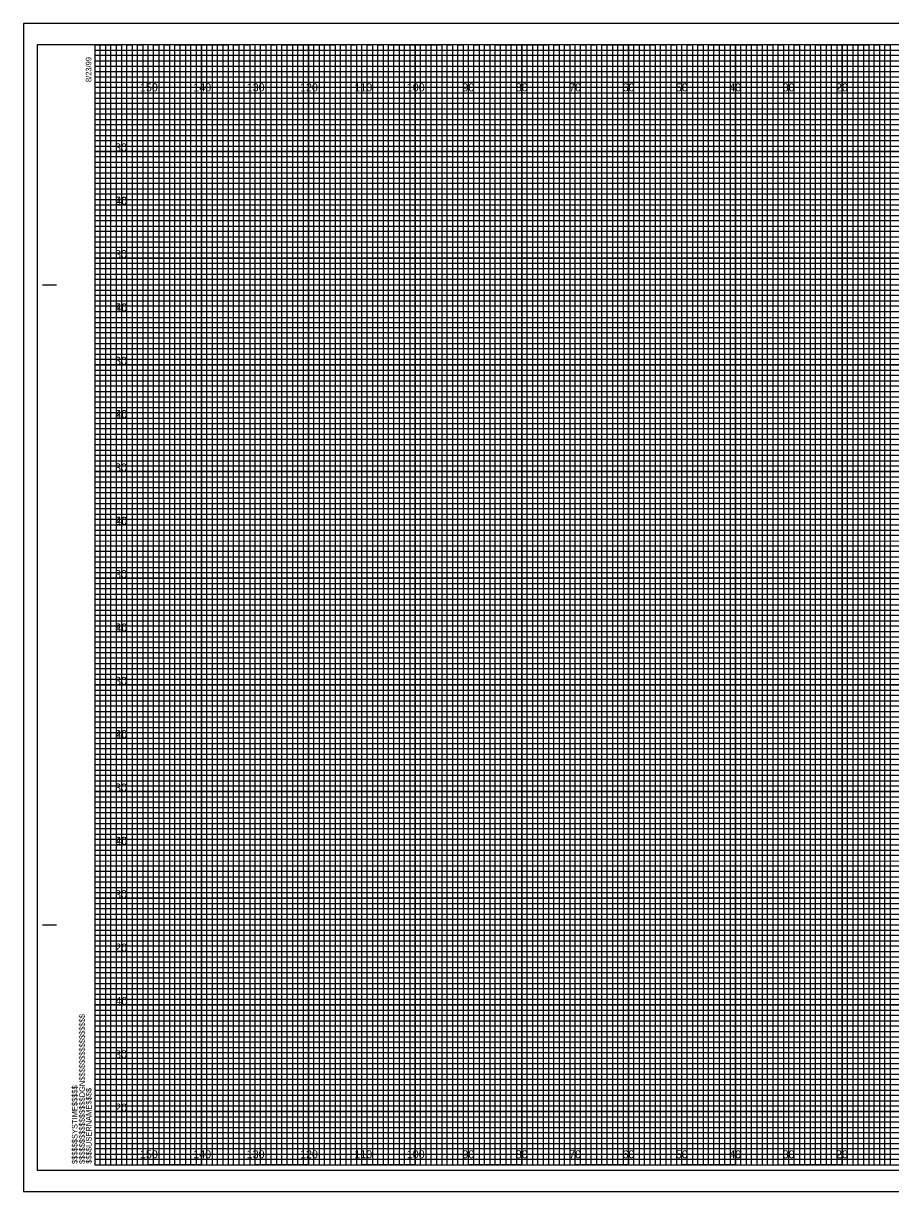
# Model space of a CAD drawing. Extents: x -13 to 323, y 215 to 434.
# Drawn here: x -13.4 to 149.1, y 215 to 434 of the extents above; entities that cross this region are included whole.
import ezdxf

# ---------------------------------------------------------------- set-up
doc = ezdxf.new("R2010")
doc.units = 0
for name, color, linetype in [('Prop XS Elevation Labels', 7, 'Continuous'), ('Prop XS Offset Labels', 7, 'Continuous'), ('Sheet Cross Section CELL', 7, 'Continuous'), ('Sheet Cross Section Grid Major CELL', 7, 'Continuous'), ('Sheet Cross Section Grid Middle CELL', 7, 'Continuous'), ('Sheet Cross Section Grid Minor 1 CELL', 7, 'Continuous'), ('Sheet Cross Section Grid Minor 2 CELL', 7, 'Continuous'), ('Sheet Cutting Line CELL', 7, 'Continuous'), ('Sheet DOT Grid CELL', 7, 'Continuous'), ('Sheet Plot Border Inside CELL', 7, 'Continuous'), ('Sheet Plot Border Outside CELL', 7, 'Continuous')]:
    doc.layers.add(name, color=color, linetype=linetype)

msp = doc.modelspace()

# ---------------------------------------------------------------- linework, layer by layer
at = {"layer": 'Sheet Cross Section CELL'}
for p, q in [((-9.8, 385), (-7.3, 385)), ((-9.7, 385), (-7.2, 385)), ((-9.8, 265), (-7.3, 265)), ((-9.7, 265), (-7.2, 265)), ((0, 220), (0, 220)), ((0, 220), (0, 220)), ((0, 220), (0, 220)), ((0, 220), (0, 220)), ((0, 220), (0, 220)), ((0, 220), (0, 220)), ((0, 220), (0, 220))]:
    msp.add_line(p, q, dxfattribs=at)
msp.add_lwpolyline([(320, 430), (0, 430), (0, 220), (320, 220)], close=True, dxfattribs=at)
at = {"layer": 'Sheet Cross Section Grid Major CELL'}
for p, q in [((10, 430), (0, 430)), ((10, 220), (10, 430)), ((30, 430), (20, 430)), ((20, 430), (20, 220)), ((30, 220), (30, 430)), ((50, 430), (40, 430)), ((40, 430), (40, 220)), ((50, 220), (50, 430)), ((70, 430), (60, 430)), ((60, 430), (60, 220)), ((70, 220), (70, 430)), ((90, 430), (80, 430)), ((80, 430), (80, 220)), ((90, 220), (90, 430)), ((110, 430), (100, 430)), ((100, 430), (100, 220)), ((110, 220), (110, 430)), ((130, 430), (120, 430)), ((120, 430), (120, 220)), ((130, 220), (130, 430)), ((150, 430), (140, 430)), ((140, 430), (140, 220)), ((20, 220), (10, 220)), ((40, 220), (30, 220)), ((60, 220), (50, 220)), ((80, 220), (70, 220)), ((100, 220), (90, 220)), ((120, 220), (110, 220)), ((140, 220), (130, 220))]:
    msp.add_line(p, q, dxfattribs=at)
for points in [[(0, 420), (320, 420), (320, 410), (0, 410)], [(0, 400), (320, 400), (320, 390), (0, 390)], [(0, 380), (320, 380), (320, 370), (0, 370)], [(0, 360), (320, 360), (320, 350), (0, 350)], [(0, 340), (320, 340), (320, 330), (0, 330)], [(0, 320), (320, 320), (320, 310), (0, 310)], [(0, 300), (320, 300), (320, 290), (0, 290)], [(0, 280), (320, 280), (320, 270), (0, 270)], [(0, 260), (320, 260), (320, 250), (0, 250)], [(0, 240), (320, 240), (320, 230), (0, 230)]]:
    msp.add_lwpolyline(points, dxfattribs=at)
at = {"layer": 'Sheet Cross Section Grid Middle CELL'}
for points in [[(0, 430), (5, 430), (5, 220), (15, 220), (15, 430), (25, 430), (25, 220), (35, 220), (35, 430), (45, 430), (45, 220), (55, 220), (55, 430), (65, 430), (65, 220), (75, 220), (75, 430), (85, 430), (85, 220), (95, 220), (95, 430), (105, 430), (105, 220), (115, 220), (115, 430), (125, 430), (125, 220), (135, 220), (135, 430), (145, 430), (145, 220), (155, 220)], [(0, 425), (275, 425)], [(0, 405), (320, 405), (320, 415), (0, 415)], [(0, 385), (320, 385), (320, 395), (0, 395)], [(0, 365), (320, 365), (320, 375), (0, 375)], [(0, 345), (320, 345), (320, 355), (0, 355)], [(0, 325), (320, 325), (320, 335), (0, 335)], [(0, 305), (320, 305), (320, 315), (0, 315)], [(0, 285), (320, 285), (320, 295), (0, 295)], [(0, 265), (320, 265), (320, 275), (0, 275)], [(0, 245), (320, 245), (320, 255), (0, 255)], [(0, 225), (320, 225), (320, 235), (0, 235)]]:
    msp.add_lwpolyline(points, dxfattribs=at)
at = {"layer": 'Sheet Cross Section Grid Minor 1 CELL'}
for p, q in [((0, 429), (260, 429)), ((260, 427.98), (0, 427.98)), ((0, 427.98), (0, 427)), ((0, 427), (260, 427)), ((260, 425.89), (0, 425.89)), ((0, 425.89), (0, 424)), ((0, 424), (320, 424))]:
    msp.add_line(p, q, dxfattribs=at)
for points in [[(0, 423), (270, 423), (320, 423), (320, 422), (0, 422)], [(0, 421), (320, 421), (320, 419), (0, 419)], [(0, 418), (320, 418), (320, 417), (0, 416.98)], [(0, 416), (320, 416), (320, 414), (0, 414)], [(0, 413), (320, 413), (320, 412), (0, 412)], [(0, 411), (320, 411), (320, 409), (0, 409)], [(0, 408), (320, 408), (320, 407), (0, 407)], [(0, 406), (320, 406), (320, 404), (0, 404)], [(0, 403), (320, 403), (320, 402), (0, 402)], [(0, 401), (320, 401), (320, 399), (0, 399)], [(0, 398), (320, 398), (320, 397), (0, 397)], [(0, 396), (320, 396), (320, 393.95), (320, 393), (320, 392), (0, 392)], [(0, 394), (320, 394), (320, 393), (0, 393)], [(0, 391), (320, 391), (320, 389), (0, 389.03)], [(0, 389.03), (320, 389), (320, 388), (0, 388)], [(0, 387), (320, 387), (320, 386), (0, 386)], [(0, 384), (320, 384), (320, 383), (0, 383)], [(0, 382), (320, 382), (320, 381), (0, 381)], [(-0.07, 378.89), (320, 378.89), (320, 377.88), (-0.07, 377.88)], [(0, 377), (320, 377), (320, 376), (0, 376)], [(0, 374), (320, 374), (320, 373), (0, 373)], [(0, 372), (320, 372), (320, 371), (0, 371)], [(0, 369), (320, 369), (320, 368), (0, 368)], [(0, 367), (320, 367), (320, 366), (0, 366)], [(0, 364), (320, 364), (320, 363), (0, 363)], [(0, 362), (320, 362), (320, 361), (0, 361)], [(0, 359), (320, 359), (319.99, 357.98), (0, 358)], [(0, 357), (320, 357), (320, 356), (0, 356)], [(0, 354), (320, 354), (320, 353), (0, 353)], [(0, 352), (320, 352), (320, 351), (0, 351)], [(0, 349), (320, 349), (320, 348), (0, 348)], [(0, 347), (320, 347), (320, 346), (0, 346)], [(0, 344), (320, 344), (320, 343), (0, 343)], [(0, 342), (320, 342), (320, 341), (0, 341)], [(0, 339), (320, 339), (320, 338), (0, 338)], [(0, 336.99), (320.07, 336.91), (320, 336), (0, 336)], [(0, 334), (320, 334), (320, 333), (0, 333)], [(0, 332), (320, 332), (320, 331), (0, 331)], [(0, 329), (320, 329), (320, 328), (0, 328)], [(0, 327), (320, 327), (320, 326), (0, 326)], [(0, 324), (320, 324), (320, 323), (0, 323)], [(0, 322), (320, 322), (320, 321), (0, 321)], [(0, 319), (320, 319), (320, 318), (0, 318)], [(0, 317), (320, 317), (320, 316), (0, 316)], [(0, 314), (320, 314), (320, 313), (0, 313)], [(0, 312), (320, 312), (320, 311), (0, 311)], [(0, 309), (320, 309), (320, 308), (0, 308)], [(0, 307), (320, 307), (320, 306), (0, 306)], [(0, 304), (320, 304), (320, 303), (0, 303)], [(0, 302), (320, 302), (320, 301), (0, 301)], [(0, 299), (320, 299), (319.99, 297.98), (0, 298)], [(0, 297), (320, 297), (320, 296), (0, 296)], [(0, 294), (320, 294), (320, 293), (0, 293)], [(0, 292), (320, 292), (320, 291), (0, 291)], [(0, 289), (320, 289), (320, 288), (0, 288)], [(0, 287), (320, 287), (320, 286), (0, 286)], [(0, 284), (320, 284), (320, 283), (0, 283)], [(0, 282), (320, 282), (320, 281), (0, 281)], [(0, 279), (320, 279), (320, 278), (0, 278)], [(0, 276.99), (320.07, 276.91), (320, 276), (0, 276)], [(0, 274), (320, 274), (320, 273), (0, 273)], [(0, 272), (320, 272), (320, 271), (0, 271)], [(0, 269), (320, 269), (320, 268), (0, 268)], [(0, 267), (320, 267), (320, 266), (0, 266)], [(0, 264), (320, 264), (320, 263), (0, 263)], [(0, 262), (320, 262), (320, 261), (0, 261)], [(0, 259), (320, 259), (320, 258), (0, 258)], [(0, 257), (320, 257), (320, 256), (0, 256)], [(0, 254), (320, 254), (320, 253), (0, 253)], [(0, 252), (320, 252), (320, 251), (0, 251)], [(0, 249), (320, 249), (320, 248), (0, 248)], [(0, 247), (320, 247), (320, 246), (0, 246)], [(0, 244), (320, 244), (320, 243), (0, 243)], [(0, 242), (320, 242), (320, 241), (0, 241)], [(0, 239), (320, 239), (320, 238), (0, 238)], [(0, 237), (320, 237), (320, 236), (0, 236)], [(0, 234), (320, 234), (320, 233), (0, 233)], [(0, 232), (320, 232), (320, 231), (0, 231)], [(0, 229), (320, 229), (320, 228), (0, 228)], [(0, 227), (320, 227), (320, 226), (0, 226)], [(0, 224), (320, 224), (320, 223), (0, 223)], [(0, 222), (320, 222), (320, 221), (0, 221)]]:
    msp.add_lwpolyline(points, dxfattribs=at)
at = {"layer": 'Sheet Cross Section Grid Minor 2 CELL'}
for points in [[(0, 220), (1, 220), (1, 430), (2, 430), (2, 220)], [(2, 220), (3, 220), (3, 430), (4, 430), (4, 220)], [(5, 220), (6, 220), (6, 430), (7, 430), (7, 220)], [(7, 220), (8, 220), (8, 430), (9, 430), (9, 220)], [(10, 220), (11, 220), (11, 430), (12, 430), (12, 220)], [(12, 220), (13, 220), (13, 430), (14, 430), (14, 220)], [(15, 220), (16, 220), (16, 430), (17, 430), (17, 220)], [(17, 220), (18, 220), (18, 430), (19, 430), (19, 220)], [(20, 220), (21, 220), (21, 430), (22, 430), (22, 220)], [(22, 220), (23, 220), (23, 430), (24, 430), (24, 220)], [(25, 220), (26, 220), (26, 430), (27, 430), (27, 220)], [(27, 220), (28, 220), (28, 430), (29, 430), (29, 220)], [(30, 220), (31, 220), (31, 430), (32, 430), (32, 220)], [(32, 220), (33, 220), (33, 430), (34, 430), (34, 220)], [(35, 220), (36, 220), (36, 430), (37, 430), (37, 220)], [(37, 220), (38, 220), (38, 430), (39, 430), (39, 220)], [(40, 220), (41, 220), (41, 430), (42, 430), (42, 220)], [(42, 220), (43, 220), (43, 430), (44, 430), (44, 220)], [(45, 220), (46, 220), (46, 430), (47, 430), (47, 220)], [(47, 220), (48, 220), (48, 430), (49, 430), (49, 220)], [(50, 220), (51, 220), (51, 430), (52, 430), (52, 220)], [(52, 220), (53, 220), (53, 430), (54, 430), (54, 220)], [(55, 220), (56, 220), (56, 430), (57, 430), (57, 220)], [(57, 220), (58, 220), (58, 430), (59, 430), (59, 220)], [(60, 220), (61, 220), (61, 430), (62, 430), (62, 220)], [(62, 220), (63, 220), (63, 430), (64, 430), (64, 220)], [(65, 220), (66, 220), (66, 430), (67, 430), (67, 220)], [(67, 220), (68, 220), (68, 430), (69, 430), (69, 220)], [(70, 220), (71, 220), (71, 430), (72, 430), (72, 220)], [(72, 220), (73, 220), (73, 430), (74, 430), (74, 220)], [(75, 220), (76, 220), (76, 430), (77, 430), (77, 220)], [(77, 220), (78, 220), (78, 430), (79, 430), (79, 220)], [(80, 220), (81, 220), (81, 430), (82, 430), (82, 220)], [(82, 220), (83, 220), (83, 430), (84, 430), (84, 220)], [(85, 220), (86, 220), (86, 430), (87, 430), (87, 220)], [(87, 220), (88, 220), (88, 430), (89, 430), (89, 220)], [(90, 220), (91, 220), (91, 430), (92, 430), (92, 220)], [(92, 220), (93, 220), (93, 430), (94, 430), (94, 220)], [(95, 220), (96, 220), (96, 430), (97, 430), (97, 220)], [(97, 220), (98, 220), (98, 430), (99, 430), (99, 220)], [(100, 220), (101, 220), (101, 430), (102, 430), (102, 220)], [(102, 220), (103, 220), (103, 430), (104, 430), (104, 220)], [(105, 220), (106, 220), (106, 430), (107, 430), (107, 220)], [(107, 220), (108, 220), (108, 430), (109, 430), (109, 220)], [(110, 220), (111, 220), (111, 430), (112, 430), (112, 220)], [(112, 220), (113, 220), (113, 430), (114, 430), (114, 220)], [(115, 220), (116, 220), (116, 430), (117, 430), (117, 220)], [(117, 220), (118, 220), (118, 430), (119, 430), (119, 220)], [(120, 220), (121, 220), (121, 430), (122, 430), (122, 220)], [(122, 220), (123, 220), (123, 430), (124, 430), (124, 220)], [(125, 220), (126, 220), (126, 430), (127, 430), (127, 220)], [(127, 220), (128, 220), (128, 430), (129, 430), (129, 220)], [(130, 220), (131, 220), (131, 430), (132, 430), (132, 220)], [(132, 220), (133, 220), (133, 430), (134, 430), (134, 220)], [(135, 220), (136, 220), (136, 430), (137, 430), (137, 220)], [(137, 220), (138, 220), (138, 430), (139, 430), (139, 220)], [(140, 220), (141, 220), (141, 430), (142, 430), (142, 220)], [(142, 220), (143, 220), (143, 430), (144, 430), (144, 220)], [(145, 220), (146, 220), (146, 430), (147, 430), (147, 220)], [(147, 220), (148, 220), (148, 430), (149, 430), (149, 220)]]:
    msp.add_lwpolyline(points, dxfattribs=at)
at = {"layer": 'Sheet Cutting Line CELL'}
for p, q in [((323.3, 434), (-13.4, 434)), ((-13.4, 434), (-13.4, 215)), ((-13.4, 215), (323.3, 215))]:
    msp.add_line(p, q, dxfattribs=at)
at = {"layer": 'Sheet DOT Grid CELL'}
for p, q in [((10, 220), (10, 430)), ((20, 220), (20, 430)), ((30, 220), (30, 430)), ((40, 220), (40, 430)), ((50, 220), (50, 430)), ((60, 220), (60, 430)), ((70, 220), (70, 430)), ((80, 220), (80, 430)), ((90, 220), (90, 430)), ((100, 220), (100, 430)), ((110, 220), (110, 430)), ((120, 220), (120, 430)), ((130, 220), (130, 430)), ((140, 220), (140, 430)), ((0, 420), (320, 420)), ((0, 410), (320, 410)), ((0, 400), (320, 400)), ((0, 390), (320, 390)), ((0, 380), (320, 380)), ((0, 370), (320, 370)), ((0, 360), (320, 360)), ((0, 350), (320, 350)), ((0, 340), (320, 340)), ((0, 330), (320, 330)), ((0, 320), (320, 320)), ((0, 310), (320, 310)), ((0, 300), (320, 300)), ((0, 290), (320, 290)), ((0, 280), (320, 280)), ((0, 270), (320, 270)), ((0, 260), (320, 260)), ((0, 250), (320, 250)), ((0, 240), (320, 240)), ((0, 230), (320, 230))]:
    msp.add_line(p, q, dxfattribs=at)
at = {"layer": 'Sheet Plot Border Inside CELL'}
msp.add_lwpolyline([(-10.8, 219), (322.4, 219), (322.4, 430), (-10.8, 430)], close=True, dxfattribs=at)
at = {"layer": 'Sheet Plot Border Outside CELL'}
msp.add_lwpolyline([(-13.4, 215), (323.3, 215), (323.3, 434), (-13.4, 434)], close=True, dxfattribs=at)

# ---------------------------------------------------------------- texts
at = {"layer": 'Prop XS Elevation Labels'}
for s, p in [('30', (3.78, 410)), ('20', (3.8, 400)), ('40', (3.87, 400)), ('30', (3.78, 390)), ('20', (3.8, 380)), ('40', (3.87, 380)), ('30', (3.78, 370)), ('20', (3.8, 360)), ('40', (3.87, 360)), ('30', (3.78, 350)), ('20', (3.8, 340)), ('40', (3.87, 340)), ('30', (3.78, 330)), ('20', (3.8, 320)), ('40', (3.87, 320)), ('30', (3.78, 310)), ('20', (3.8, 300)), ('40', (3.87, 300)), ('30', (3.78, 290)), ('20', (3.8, 280)), ('40', (3.87, 280)), ('30', (3.78, 270)), ('20', (3.8, 260)), ('40', (3.87, 250)), ('30', (3.78, 240)), ('20', (3.8, 230))]:
    msp.add_text(s, height=1.5, dxfattribs=at).set_placement(p)
at = {"layer": 'Prop XS Offset Labels'}
for s, p in [('150', (8.44, 421.25)), ('140', (18.44, 421.25)), ('130', (28.44, 421.25)), ('120', (38.44, 421.25)), ('110', (48.62, 421.25)), ('100', (58.44, 421.25)), ('90', (68.86, 421.25)), ('80', (78.86, 421.25)), ('70', (88.86, 421.25)), ('60', (98.86, 421.25)), ('50', (108.86, 421.25)), ('40', (118.86, 421.25)), ('30', (128.86, 421.25)), ('20', (138.86, 421.25)), ('150', (8.44, 221.25)), ('140', (18.44, 221.25)), ('130', (28.44, 221.25)), ('120', (38.44, 221.25)), ('110', (48.62, 221.25)), ('100', (58.44, 221.25)), ('90', (68.86, 221.25)), ('80', (78.86, 221.25)), ('70', (88.86, 221.25)), ('60', (98.86, 221.25)), ('50', (108.86, 221.25)), ('40', (118.86, 221.25)), ('30', (128.86, 221.25)), ('20', (138.86, 221.25))]:
    msp.add_text(s, height=1.5, dxfattribs=at).set_placement(p)
at = {"layer": 'Sheet Cross Section CELL'}
for s, p in [('8/23/99', (-0.65, 423)), ('$$$$$$$$$$$$$$$$DGN$$$$$$$$$$$$$$$$', (-1.88, 220.18)), ('$$$$$$SYSTIME$$$$$', (-3.26, 220.18)), ('$$$$USERNAME$$$$', (-0.62, 220.23))]:
    msp.add_text(s, height=1.05, rotation=90, dxfattribs=at).set_placement(p)

doc.saveas('drawing.dxf')
